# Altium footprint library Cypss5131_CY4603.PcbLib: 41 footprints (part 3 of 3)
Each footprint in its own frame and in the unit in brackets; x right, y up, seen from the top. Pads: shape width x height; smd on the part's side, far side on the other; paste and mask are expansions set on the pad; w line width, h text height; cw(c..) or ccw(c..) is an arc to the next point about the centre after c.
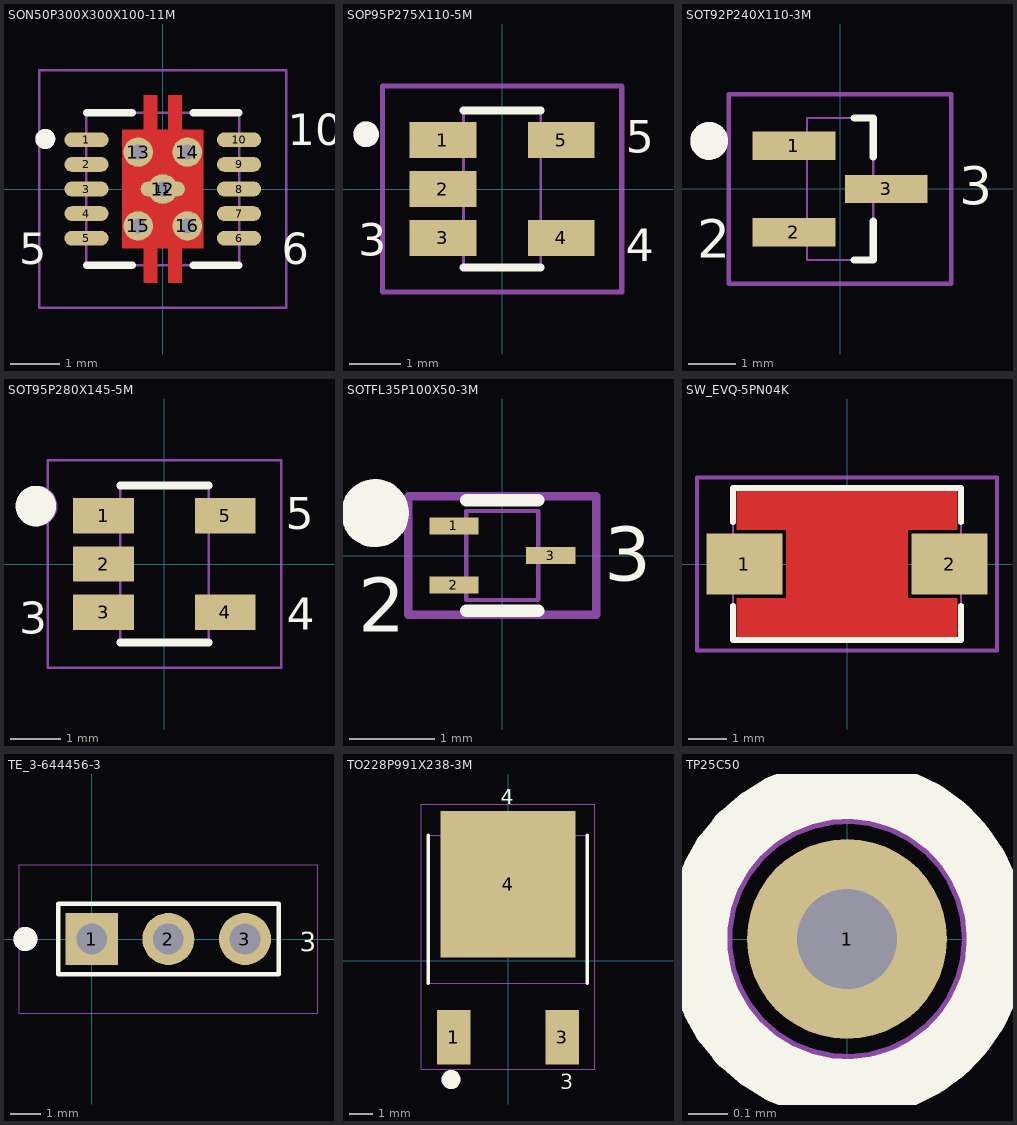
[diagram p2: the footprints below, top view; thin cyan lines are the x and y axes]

## SON50P300X300X100-11M [mm]
height 1
pads (16):
  oval 0.9x0.3 smd mask+0: 1(-1.55,1) 2(-1.55,0.5) 3(-1.55,0) 4(-1.55,-0.5) 5(-1.55,-1) 6(1.55,-1) 7(1.55,-0.5) 8(1.55,0) 9(1.55,0.5) 10(1.55,1) 11(0,0)
  round 0.6 hole 0.3 mask+0: 12(0,0) 13(-0.5,0.75) 14(0.5,0.75) 15(-0.5,-0.75) 16(0.5,-0.75)
Top Layer:
  region: 0.825,-1.2 0.825,1.2 0.39,1.2 0.39,1.9 0.11,1.9 0.11,1.2 -0.11,1.2 -0.11,1.9 -0.39,1.9 -0.39,1.2 -0.825,1.2 -0.825,-1.2 -0.39,-1.2 -0.39,-1.9 -0.11,-1.9 -0.11,-1.2 0.11,-1.2 0.11,-1.9 0.39,-1.9 0.39,-1.2
Top Overlay:
  circle w0.203: c-2.388,1.016 r0.102
  lines w0.15: -1.55,-1.55 -0.615,-1.55 ; -1.55,1.55 -0.615,1.55 ; 0.615,-1.55 1.55,-1.55 ; 0.615,1.55 1.55,1.55
  text "10" at 2.54,0.889 h0.64
  text "6" at 2.413,-1.524 h0.64
  text "5" at -2.921,-1.524 h0.64
Top Paste:
  region: -0.11,0.11 -0.79,0.11 -0.79,1.16 -0.11,1.16
  region: 0.79,0.11 0.11,0.11 0.11,1.16 0.79,1.16
  region: -0.11,-1.16 -0.79,-1.16 -0.79,-0.11 -0.11,-0.11
  region: 0.79,-1.16 0.11,-1.16 0.11,-0.11 0.79,-0.11
  region: 0.12,-1.88 0.38,-1.88 0.38,-1.38 0.12,-1.38
  region: -0.38,-1.88 -0.12,-1.88 -0.12,-1.38 -0.38,-1.38
  region: -0.38,1.38 -0.12,1.38 -0.12,1.88 -0.38,1.88
  region: 0.12,1.38 0.38,1.38 0.38,1.88 0.12,1.88
  region: 0.825,-1.2 0.825,1.2 0.39,1.2 0.39,1.9 0.11,1.9 0.11,1.2 -0.11,1.2 -0.11,1.9 -0.39,1.9 -0.39,1.2 -0.825,1.2 -0.825,-1.2 -0.39,-1.2 -0.39,-1.9 -0.11,-1.9 -0.11,-1.2 0.11,-1.2 0.11,-1.9 0.39,-1.9 0.39,-1.2
Top Solder:
  region: 0.825,-1.2 0.825,1.2 0.39,1.2 0.39,1.9 0.11,1.9 0.11,1.2 -0.11,1.2 -0.11,1.9 -0.39,1.9 -0.39,1.2 -0.825,1.2 -0.825,-1.2 -0.39,-1.2 -0.39,-1.9 -0.11,-1.9 -0.11,-1.2 0.11,-1.2 0.11,-1.9 0.39,-1.9 0.39,-1.2
Mechanical 13:
  circle w0.203: c-2.388,1.016 r0.102
  lines w0.05: -1.55,-1.55 -1.55,1.55 1.55,1.55 1.55,-1.55 -1.55,-1.55
Mechanical 14:
  text "VIA60-30-85" at -3.077,-5.298 h0.64
  text "SON50P300X300X100-11M" at -5.625,2.95 h0.64
  text "B90_30" at -1.419,-3.268 h0.64
  text "U165_380" at -1.934,-4.282 h0.64
Mechanical 15:
  lines w0.051: -2.51,-2.41 -2.51,2.41 2.51,2.41 2.51,-2.41 -2.51,-2.41
3D body: height 1, standoff 0, extent -1.549,-1.549 1.549,1.549

## SOP95P275X110-5M [mm] "SOT23, 5-Leads, Body 3.0x3.0mm (max), Pitch 0.95mm, IPC Low Density"
height 1.1
pads (5):
  rect 1.3x0.7 smd mask+0: 1(-1.15,0.95) 2(-1.15,0) 3(-1.15,-0.95) 4(1.15,-0.95) 5(1.15,0.95)
Top Overlay:
  circle w0.25: c-2.641,1.062 r0.125
  lines w0.15: -0.75,-1.525 0.75,-1.525 ; -0.75,1.525 0.75,1.525
  text "5" at 2.4,0.7 h0.63
  text "4" at 2.4,-1.4 h0.63
  text "3" at -2.8,-1.3 h0.63
  text ".Designator" at -4.374,2.471 h0.8
Mechanical 13:
  circle w0.25: c-2.641,1.062 r0.125
  lines w0.05: -0.75,-1.5 0.75,-1.5 0.75,1.5 -0.75,1.5 -0.75,-1.5
  text ".Designator" at -4.374,-0.183 h0.8
Mechanical 14:
  text "R130_70" at -2.653,-3.368 h0.8
  text "SOP95P275X110-5M" at -6.246,3.825 h0.8
Mechanical 15:
  lines w0.1: -2.325,-2 2.325,-2 2.325,2 -2.325,2 -2.325,-2
3D body: height 1.1, standoff 0.01, extent -0.75,-1.5 0.75,1.5

## SOT92P240X110-3M [mm] "SOT23, 3-Leads, Body 3.0x2.5mm (max), Pitch 0.92mm, IPC Low Density"
height 1.1
pads (3):
  rect 1.75x0.6 smd mask+0: 1(-0.975,0.915) 2(-0.975,-0.915) 3(0.975,0)
Top Overlay:
  circle w0.4: c-2.765,1.016 r0.2
  lines w0.152: 0.3,-1.5 0.7,-1.5 0.7,-0.676 ; 0.3,1.5 0.7,1.5 0.7,0.676
  text ".Designator" at -3.106,2.464 h0.64
  text "2" at -3.023,-1.448 h0.8
  text "3" at 2.515,-0.33 h0.8
Mechanical 13:
  circle w0.4: c-2.765,1.016 r0.2
  lines w0.05: -0.7,-1.5 0.7,-1.5 0.7,1.5 -0.7,1.5 -0.7,-1.5
  text ".Designator" at -3.547,-0.134 h0.64
Mechanical 14:
  text "R60_175" at -2.572,-4.08 h0.64
  text "SOT92P240X110-3M" at -5.791,4.166 h0.8
Mechanical 15:
  lines w0.1: -2.35,-2 2.35,-2 2.35,2 -2.35,2 -2.35,-2
3D body: height 1.1, standoff 0.1, extent -0.7,-1.5 0.7,1.5

## SOT95P280X145-5M [mm] "SOT23, 5-Leads, Body 3.1x2.8mm (max), Pitch 0.95mm, IPC Low Density"
height 1.45
pads (5):
  rect 1.2x0.7 smd mask+0: 1(-1.2,0.95) 2(-1.2,0) 3(-1.2,-0.95) 4(1.2,-0.95) 5(1.2,0.95)
Top Overlay:
  circle w0.4: c-2.537,1.143 r0.2
  lines w0.152: -0.875,-1.55 0.875,-1.55 ; -0.875,1.55 0.875,1.55
  text "5" at 2.388,0.686 h0.64
  text "4" at 2.413,-1.295 h0.64
  text "3" at -2.87,-1.372 h0.64
  text ".Designator" at -2.979,2.54 h0.64
Mechanical 13:
  lines w0.05: -0.875,-1.55 0.875,-1.55 0.875,1.55 -0.875,1.55 -0.875,-1.55
  lines w0.4: -2.311,1.143 cw(c-2.511,1.143) -2.312,1.154
  text ".Designator" at -3.191,-0.261 h0.64
Mechanical 14:
  text "R70_120" at -1.981,-3.353 h0.64
  text "SOT95P280X145-5M" at -6.02,3.988 h0.8
Mechanical 15:
  lines w0.05: -2.3,-2.05 2.3,-2.05 2.3,2.05 -2.3,2.05 -2.3,-2.05
3D body: height 1.45, standoff 0.15, extent -0.875,-1.55 0.875,1.55

## SOTFL35P100X50-3M [mm]
height 0.5
pads (3):
  rect 0.58x0.2 smd mask+0: 1(-0.57,0.35) 2(-0.57,-0.35) 3(0.57,0)
Top Overlay:
  circle w0.4: c-1.5,0.5 r0.2
  lines w0.15: -0.425,-0.65 0.425,-0.65 ; -0.425,0.65 0.425,0.65
  text "3" at 1.2,-0.3 h0.64
  text "2" at -1.7,-0.9 h0.64
  text ".Designator" at -4.013,1.196 h0.8
Mechanical 13:
  circle w0.4: c-1.5,0.5 r0.2
  lines w0.05: -0.425,-0.525 -0.425,0.525 0.425,0.525 0.425,-0.525 -0.425,-0.525
  text ".Designator" at -4,-0.4 h0.8
Mechanical 14:
  text "R58_20" at -2.667,-1.956 h0.8
  text "SOTFL35P100X50-3M" at -6.8,2.2 h0.8
Mechanical 15:
  lines w0.1: -1.11,-0.7 -1.11,0.7 1.11,0.7 1.11,-0.7 -1.11,-0.7
3D body: height 0.5, standoff 0, extent -0.45,-0.55 0.45,0.55

## SW_EVQ-5PN04K [mm]
height 4.3
pads (2):
  rect 2x1.6 smd mask+0: 1(-2.7,0) 2(2.7,0)
Top Layer:
  region: -2.9,2 -2.9,0.9 -1.6,0.9 -1.6,-0.9 -2.9,-0.9 -2.9,-2 2.9,-2 2.9,-0.9 1.6,-0.9 1.6,0.9 2.9,0.9 2.9,2
Top Overlay:
  lines w0.15: -3,-1.1 -3,-2 3,-2 3,-1.1 ; -3,1.1 -3,2 3,2 3,1.1
  text ".Designator" at -3.957,2.767 h0.8
Mechanical 13:
  lines w0.05: -3,-2 -3,2 3,2 3,-2 -3,-2
  text ".Designator" at -3.706,-0.27 h0.8
Mechanical 14:
  text "SW_EVQ-5PN04K" at -4.7,4.125 h0.8
  text "R200_160" at -3.025,-3.4 h0.8
Mechanical 15:
  lines w0.1: -3.95,-2.275 3.95,-2.275 3.95,2.275 -3.95,2.275 -3.95,-2.275
3D body: height 4.3, standoff 0, extent -2.999,-1.999 2.999,1.999

## TE_3-644456-3 [mil]
height 405
pads (3):
  rect 68x68 / inner round 68 / far side rect 68x68 hole 40 mask+0: 1(0,0)
  round 68 hole 40 mask+0: 2(100,0) 3(200,0)
Top Overlay:
  circle w15.75: c-86.61,0 r7.87
  lines w6: -44,-46 -44,46 244,46 244,-46 -44,-46
  text ".Designator" at -53.61,119.3 h31.5
  text "3" at 271.65,-15.75 h25
Mechanical 13:
  circle w15.75: c-86.61,0 r7.87
  lines w2: -44,-46 244,-46 244,46 -44,46 -44,-46
  text ".Designator" at -58.55,-3.31 h31.5
Mechanical 14:
  text "C172H102" at 7.7,-146.12 h31.5
  text "TE_3-644456-3" at -97.78,172.86 h31.5
  text "S172H102" at 7.7,-194.12 h31.5
Mechanical 15:
  lines w1: -95,-97 -95,97 295,97 295,-97 -95,-97
3D body: height 405, standoff 0, extent -45,-47 245,47

## TO228P991X238-3M [mil]
height 94
pads (3):
  rect 55x90 smd mask+0: 1(-90,-126.75) 3(90,-126.75)
  rect 224x243 smd mask+0: 4(0,126.75)
Top Overlay:
  circle w15.75: c-94.49,-196.85 r7.87
  lines w6: -132.5,-37.13 -132.5,207.87 ; 131.5,-37.13 131.5,207.87
  text "4" at -11.81,259.84 h25
  text "3" at 86.61,-212.6 h25
  text ".Designator" at -153.65,288.66 h31.5
Mechanical 13:
  circle w15.75: c-94.49,-196.85 r7.87
  lines w2: -132.5,-37.13 132.5,-37.13 132.5,207.87 -132.5,207.87 -132.5,-37.13
  text ".Designator" at -163.96,47.4 h31.5
Mechanical 14:
  text "TO228P991X238-3M" at -242.46,335.45 h31.5
  text "R139_228" at -110.24,-326.77 h31.5
  text "R569_618" at -114.42,-270.99 h31.5
Mechanical 15:
  lines w1: -143.5,-180.13 -143.5,259.87 143.5,259.87 143.5,-180.13 -143.5,-180.13
3D body: height 94, standoff 0, extent -133.5,-38.13 133.5,208.87

## TP25C50 [mil]
height 94
pads (1):
  round 20 hole 10 mask+0: 1(0,0)
Top Overlay:
  circle w6: c0,0 r15
  text ".Designator" at -122.05,31.5 h25
Mechanical 13:
  circle w2: c0,0 r12.5
  text ".Designator" at -125.98,-39.37 h25
Mechanical 14:
  text "TP25C50" at -82.68,66.93 h25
